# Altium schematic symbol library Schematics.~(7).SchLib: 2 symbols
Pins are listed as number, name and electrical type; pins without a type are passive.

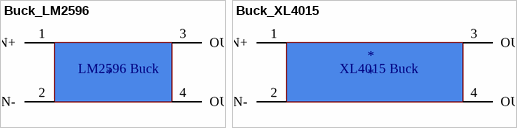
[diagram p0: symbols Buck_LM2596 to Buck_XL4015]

## Buck_LM2596
designator ?
footprint Model Name (Footprint not found)
footprint Buck_LM2596
pins: 1 IN+ (power), 2 IN- (power), 3 OUT+ (power), 4 OUT- (power)

## Buck_XL4015
designator *
footprint Buck_LM4015
pins: 1 IN+ (power), 2 IN- (power), 3 OUT+ (power), 4 OUT- (power)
